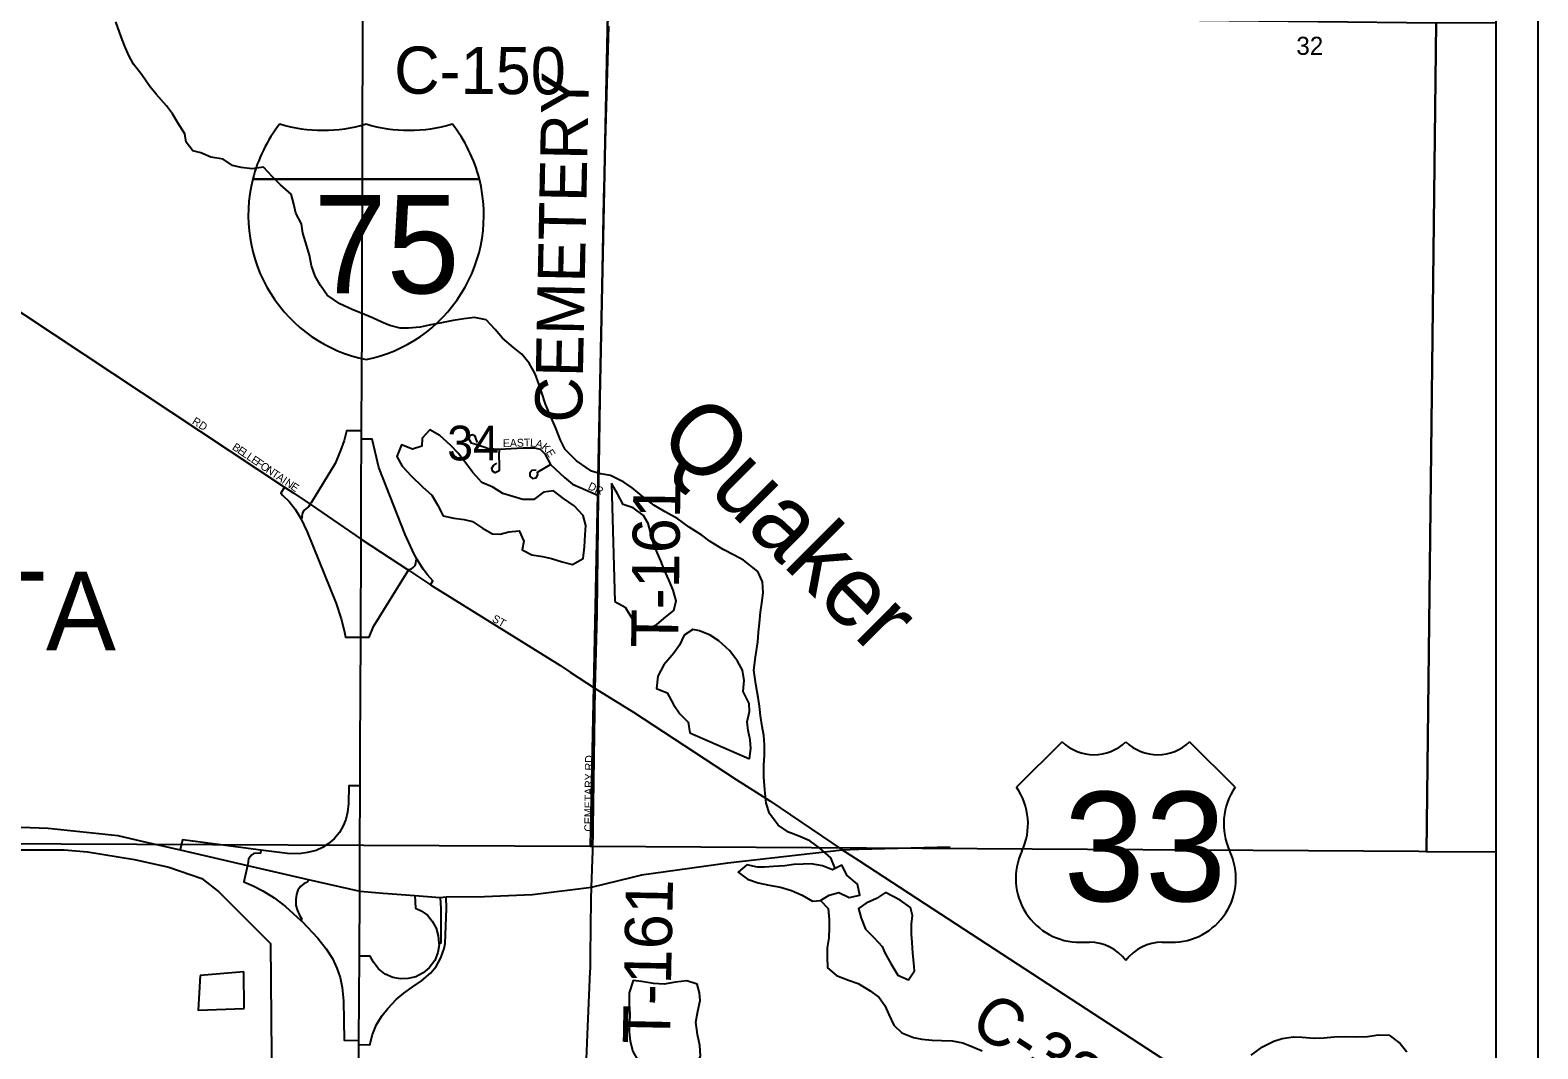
# Model space of a CAD drawing. Extents: x -784 to 1375, y -225 to 440.
# Drawn here: x 133.1 to 205.1, y 307.5 to 356.1 of the extents above; entities that cross this region are included whole.
import ezdxf

# ---------------------------------------------------------------- set-up
doc = ezdxf.new("R2010")
doc.units = 0
for name, color, linetype in [('GM_X_City_Street', 7, 'Continuous'), ('GM_X_City_Street_Text', 7, 'Continuous'), ('GM_X_Corporation_Text', 7, 'Continuous'), ('GM_X_County_Road', 7, 'Continuous'), ('GM_X_County_Road_Text', 7, 'Continuous'), ('GM_X_Interchange_Ramps', 7, 'Continuous'), ('GM_X_Interstate_Route', 7, 'Continuous'), ('GM_X_Interstate_Shield', 7, 'Continuous'), ('GM_X_Minor_Lake', 7, 'Continuous'), ('GM_X_Minor_River', 7, 'Continuous'), ('GM_X_Minor_River_Text', 7, 'Continuous'), ('GM_X_Section', 7, 'Continuous'), ('GM_X_Section_Text', 7, 'Continuous'), ('GM_X_Township_Road', 7, 'Continuous'), ('GM_X_Township_Road_Text', 7, 'Continuous'), ('GM_X_Township_Subdivision', 7, 'Continuous'), ('GM_X_Township_Subdivision_Text', 7, 'Continuous'), ('GM_X_US_Location', 7, 'Continuous'), ('GM_X_US_Route', 7, 'Continuous'), ('GM_X_US_Shield', 7, 'Continuous'), ('SH_Data', 7, 'Continuous'), ('SH_Text', 7, 'Continuous')]:
    doc.layers.add(name, color=color, linetype=linetype)

msp = doc.modelspace()

# ---------------------------------------------------------------- linework, layer by layer
at = {"layer": 'GM_X_City_Street'}
for points in [[(126.452, 346.784), (128.669, 345.259), (142.616, 336.025)], [(142.616, 336.025), (145.259, 334.275), (145.695, 333.991), (146.472, 333.461), (148.912, 331.797), (151.169, 330.314), (152.221, 329.626), (158.401, 325.779), (158.893, 325.455)], [(158.893, 325.455), (160.087, 324.667)], [(159.906, 315.192), (159.967, 316.92), (160.087, 324.667)], [(129.862, 302.524), (129.911, 316.968), (134.73, 316.967), (135.85, 316.872), (138.098, 316.511), (139.727, 316.14), (141.314, 315.604), (142.118, 314.974), (144.593, 312.499), (144.675, 301.856), (146.016, 301.248)]]:
    msp.add_lwpolyline(points, dxfattribs=at)
at = {"layer": 'GM_X_County_Road'}
for points in [[(160.087, 324.667), (161.91, 323.537), (164.313, 321.971), (166.824, 320.321), (168.42, 319.311), (171.871, 316.977)], [(171.871, 316.977), (172.668, 316.458), (175.843, 314.388)], [(175.843, 314.388), (191.895, 303.924), (193.049, 303.183), (193.82, 302.693), (195.033, 301.892), (196.331, 301.073), (199.02, 299.303)]]:
    msp.add_lwpolyline(points, dxfattribs=at)
at = {"layer": 'GM_X_Interchange_Ramps'}
for points in [[(148.933, 336.967), (148.218, 336.97), (148.215, 336.954), (148.106, 336.508), (147.932, 336.024), (147.667, 335.414), (146.525, 333.538), (146.472, 333.461)], [(152.221, 329.626), (152.34, 329.807), (152.078, 330.094), (151.879, 330.367), (151.595, 330.834), (151.446, 331.08), (151.017, 332.023), (149.765, 335.222), (149.576, 335.968), (149.443, 336.563), (148.931, 336.566)], [(145.259, 334.275), (145.076, 333.992), (145.182, 333.888), (145.484, 333.589), (145.761, 333.222), (146.029, 332.782), (146.341, 332.151), (147.728, 328.721), (147.967, 328.001), (148.104, 327.446), (148.16, 327.127), (148.893, 327.124)], [(146.472, 333.461), (146.393, 333.346), (146.266, 333.253), (146.185, 333.168), (146.111, 333.05), (146.092, 332.975), (146.087, 332.881), (146.099, 332.824), (146.029, 332.782)], [(151.169, 330.314), (151.194, 330.353), (151.322, 330.384), (151.404, 330.442), (151.487, 330.541), (151.529, 330.641), (151.533, 330.796), (151.595, 330.834)], [(148.893, 327.124), (149.298, 327.121), (149.511, 327.624), (151.057, 330.143), (151.169, 330.314)], [(148.865, 320.03), (148.331, 320.033), (148.302, 319.18), (148.258, 318.761), (148.181, 318.42), (148.06, 318.11), (147.876, 317.794), (147.626, 317.503), (147.346, 317.259), (147.07, 317.076), (146.771, 316.945), (146.352, 316.84), (145.961, 316.785), (145.39, 316.791), (144.126, 316.957), (140.882, 317.381), (140.383, 317.449), (140.273, 316.969)], [(144.126, 316.957), (144.105, 316.805), (143.795, 316.802), (143.697, 316.727), (143.593, 316.62), (143.531, 316.519), (143.515, 316.431), (143.521, 316.344), (143.494, 316.228)], [(143.494, 316.228), (143.313, 315.443), (143.752, 315.256), (144.218, 315.016), (144.756, 314.676), (145.306, 314.262), (146.038, 313.604), (146.099, 313.549), (146.853, 312.751), (147.242, 312.24), (147.544, 311.78), (147.76, 311.321), (147.915, 310.875), (148.008, 310.405), (148.074, 309.763), (148.11, 307.882), (148.807, 307.878)], [(146.387, 315.562), (146.357, 315.433), (146.187, 315.358), (146.023, 315.226), (145.887, 315.045), (145.821, 314.841), (145.796, 314.609), (145.8, 314.333), (145.853, 314.1), (145.963, 313.845), (146.088, 313.66), (146.038, 313.604)], [(148.806, 307.674), (149.324, 307.671), (149.454, 308.158), (149.652, 308.635), (149.919, 309.067), (150.185, 309.404), (150.583, 309.835), (150.945, 310.127), (151.35, 310.409), (151.798, 310.718), (152.222, 311.079), (152.488, 311.398), (152.72, 311.822), (152.874, 312.265), (152.92, 312.5), (152.994, 314.174), (152.971, 314.723)], [(151.472, 314.785), (151.511, 314.184), (151.771, 314.067), (152.083, 313.845), (152.297, 313.564), (152.493, 313.23), (152.585, 312.871), (152.624, 312.51), (152.632, 312.443), (152.575, 312.068), (152.43, 311.695), (152.155, 311.332), (151.873, 311.101), (151.531, 310.913), (151.163, 310.831), (150.796, 310.818), (150.431, 310.883), (150.058, 311.045), (149.747, 311.293), (149.498, 311.602), (149.348, 311.892), (148.828, 311.894)], [(152.685, 314.703), (152.715, 314.169), (152.72, 312.52), (152.624, 312.51)]]:
    msp.add_lwpolyline(points, dxfattribs=at)
at = {"layer": 'GM_X_Interstate_Route'}
for points in [[(148.956, 342.85), (148.994, 356.971), (149.127, 363.092), (149.481, 366.399), (149.866, 368.87), (150.415, 371.5), (150.759, 372.833), (151.182, 374.134), (153.143, 379.365), (157.84, 391.358), (159.301, 395.248), (160.005, 397.139)], [(148.937, 338.143), (148.939, 338.63), (148.956, 342.806), (148.956, 342.85), (148.956, 342.85)], [(148.931, 336.566), (148.931, 336.566), (148.933, 336.967), (148.937, 338.143)], [(148.922, 334.182), (148.931, 336.566)], [(148.918, 333.387), (148.92, 333.903), (148.922, 334.182)], [(148.912, 331.797), (148.914, 332.327), (148.918, 333.387)], [(148.872, 321.803), (148.893, 327.124), (148.912, 331.797)], [(148.868, 320.739), (148.872, 321.803)], [(148.845, 314.996), (148.853, 316.941), (148.865, 320.03), (148.868, 320.739)], [(148.756, 298.078), (148.806, 307.674), (148.807, 307.878), (148.828, 311.894), (148.845, 314.996)]]:
    msp.add_lwpolyline(points, dxfattribs=at)
at = {"layer": 'GM_X_Interstate_Shield'}
for p, q in [((143.736, 348.98), (154.557, 348.98)), ((154.557, 348.98), (143.736, 348.98)), ((154.557, 348.98), (143.736, 348.98))]:
    msp.add_line(p, q, dxfattribs=at)
for centre, start, end in [((150.553, 347.256), 141.66896, 165.80665), ((147.092, 358.341), 253.00908, 286.99093), ((151.201, 358.341), 253.00908, 286.99093), ((147.74, 347.256), 14.19335, 38.33104), ((150.553, 347.256), 165.80665, 258.46304), ((147.74, 347.256), 281.53696, 14.19335)]:
    msp.add_arc(centre, 7.031, start, end, dxfattribs=at)
at = {"layer": 'GM_X_Minor_Lake'}
for points in [[(152.67, 336.751), (152.192, 337.013), (151.827, 336.612), (151.807, 336.237), (151.369, 336.093), (150.846, 336.295), (150.613, 335.742), (150.878, 335.288), (151.307, 334.816), (151.841, 334.298), (152.287, 333.901), (152.551, 333.432), (152.829, 332.917), (153.339, 332.805), (153.833, 332.738), (154.223, 332.643), (154.714, 332.32), (155.191, 332.058), (155.552, 332.039)], [(155.552, 332.039), (155.959, 332.153), (156.455, 332.191), (156.674, 331.708), (156.593, 331.288), (157.056, 331.056), (157.565, 330.974), (158, 330.878), (158.508, 330.721), (159.003, 330.594), (159.517, 330.872), (159.584, 331.427), (159.607, 331.998), (159.643, 332.448), (159.514, 332.931), (159.084, 333.387), (158.578, 333.74), (158.102, 334.107), (157.621, 334.039), (157.151, 333.684), (156.625, 333.692), (155.682, 333.975), (155.206, 334.282), (154.668, 334.5), (154.239, 334.987), (153.87, 335.488), (153.545, 335.898), (153.174, 336.278), (152.67, 336.751)], [(160.871, 334.46), (161.022, 328.823)], [(163.035, 327.728), (163.461, 328.098), (163.84, 328.393), (163.952, 328.858), (163.808, 329.371), (163.604, 329.854), (163.386, 330.353), (163.226, 330.761), (163.051, 331.154), (162.891, 331.547), (162.733, 332.135), (162.618, 332.542), (162.398, 332.921), (161.907, 333.289), (161.429, 333.445), (161.15, 333.96), (160.871, 334.46)], [(161.022, 328.823), (161.514, 328.546), (161.838, 328.03), (162.043, 327.652), (162.582, 327.509), (163.035, 327.728)], [(165.074, 327.43), (164.745, 327.494), (164.336, 327.215), (164.104, 326.737), (163.844, 326.35), (163.356, 325.801), (163.078, 325.263), (163.01, 324.678), (163.518, 324.461), (163.826, 323.901), (164.121, 323.461), (164.521, 323.065), (164.605, 322.553)], [(167.457, 321.312), (167.524, 321.806), (167.484, 322.228), (167.385, 322.665), (167.345, 323.086), (167.457, 323.58), (167.432, 323.956), (167.154, 324.531), (167.206, 325.056), (167.123, 325.553), (166.873, 325.977), (166.519, 326.463), (165.984, 326.951), (165.582, 327.212), (165.074, 327.43)], [(164.605, 322.553), (167.457, 321.312)], [(167.839, 316.138), (167.33, 316.25), (166.905, 315.91), (167.351, 315.574), (167.86, 315.401), (168.399, 315.289), (168.938, 315.191), (169.462, 315.034), (169.97, 314.801), (170.462, 314.524), (170.838, 314.549)], [(170.838, 314.549), (171.262, 314.813), (171.714, 314.927), (172.207, 314.695), (172.719, 314.808), (172.606, 315.336), (172.115, 315.748), (171.867, 316.247), (171.413, 316.013), (170.935, 316.2), (170.395, 316.298), (170.02, 316.288), (169.569, 316.264), (169.132, 316.21), (168.606, 316.172), (168.17, 316.148), (167.839, 316.138)], [(173.953, 314.941), (173.513, 314.647), (173.029, 314.428), (172.651, 314.178), (172.78, 313.711), (172.983, 313.182), (173.383, 312.786), (173.783, 312.36), (173.914, 312.057)], [(173.914, 312.057), (174.193, 311.543), (174.531, 310.997), (175.039, 310.765), (175.33, 311.196), (175.305, 311.572), (175.251, 312.039), (175.213, 312.55), (175.188, 312.941), (175.194, 313.422), (175.23, 313.842), (175.145, 314.219), (174.639, 314.571), (173.953, 314.941)], [(141.227, 310.976), (141.13, 309.325), (143.324, 309.4)], [(143.318, 311.143), (141.227, 310.976)], [(143.324, 309.4), (143.318, 311.143)], [(164.469, 310.714), (163.921, 310.648), (163.379, 310.566), (162.869, 310.588), (162.299, 310.686), (161.894, 310.737), (161.706, 310.153), (161.714, 309.612), (161.738, 309.131), (161.717, 308.711), (161.711, 308.276), (161.751, 307.839), (161.879, 307.342), (162.129, 306.933), (162.637, 306.686)], [(162.637, 306.686), (162.981, 306.576), (163.46, 306.509), (163.985, 306.441), (164.466, 306.45), (164.919, 306.609), (165.121, 307.147), (165.083, 307.628), (164.969, 308.155), (164.887, 308.742), (164.984, 309.267), (165.096, 309.776), (165.071, 310.152), (164.956, 310.559), (164.469, 310.714)]]:
    msp.add_lwpolyline(points, dxfattribs=at)
at = {"layer": 'GM_X_Minor_River'}
for points in [[(139.126, 353.028), (138.83, 353.408), (138.447, 353.954), (138.048, 354.47), (137.828, 354.879), (137.61, 355.362), (137.45, 355.77), (137.204, 356.495)], [(171.549, 316.083), (171.33, 316.585), (170.811, 317.043), (170.335, 317.395), (169.782, 317.643), (169.319, 317.815), (168.828, 318.152), (168.414, 318.699), (168.256, 319.197), (168.189, 319.829), (168.137, 320.461), (168.144, 321.017), (168.166, 321.482), (168.172, 321.978), (168.133, 322.429), (168.063, 322.851), (167.98, 323.363), (167.926, 323.829), (167.871, 324.236), (167.76, 324.883), (167.663, 325.546), (167.732, 326.161), (167.846, 326.896), (167.883, 327.361), (167.933, 327.796), (167.985, 328.321), (168.053, 328.861), (168.103, 329.251), (168.079, 329.763), (167.846, 330.247), (167.162, 330.797), (166.729, 331.028), (166.192, 331.306), (165.581, 331.69), (165.18, 331.981), (164.569, 332.365), (164.033, 332.763), (163.422, 333.102), (162.885, 333.425), (162.395, 333.808), (161.845, 334.251), (161.458, 334.512), (160.816, 334.836), (160.336, 334.918), (159.917, 335.044), (159.188, 335.535), (158.654, 336.083), (158.435, 336.522), (158.202, 337.096), (157.94, 337.716), (157.721, 338.245), (157.533, 338.788), (157.389, 339.211), (157.215, 339.694), (156.936, 340.194), (156.581, 340.634), (156.18, 340.94), (155.66, 341.383), (155.305, 341.809), (154.875, 342.266), (154.321, 342.378), (153.81, 342.31), (153.313, 342.227), (152.756, 342.129), (152.153, 342.017), (151.732, 341.918), (151.175, 341.865), (150.77, 341.871), (150.29, 341.998), (149.902, 342.153), (149.454, 342.355), (149.066, 342.525), (148.483, 342.759), (147.901, 343.022), (147.29, 343.436), (146.966, 343.906), (146.717, 344.346), (146.543, 344.844), (146.444, 345.356), (146.258, 345.99), (146.128, 346.397), (146.059, 346.849), (145.795, 347.348), (145.696, 347.785), (145.567, 348.268), (145.062, 348.71), (144.662, 349.106), (144.247, 349.548), (143.705, 349.465), (143.18, 349.532), (142.776, 349.628), (142.329, 349.935), (141.745, 350.033), (141.267, 350.235), (140.877, 350.33), (140.552, 350.74), (140.498, 351.147), (140.159, 351.662), (139.91, 352.101), (139.614, 352.481), (139.126, 353.028)], [(170.838, 314.549), (171.208, 314.168), (171.261, 313.642), (171.256, 313.266), (171.235, 312.771), (171.168, 312.291), (171.163, 311.87), (171.171, 311.344), (171.602, 310.978), (172.184, 310.744), (172.633, 310.588), (173.214, 310.249), (173.646, 309.928), (173.911, 309.549), (174.1, 309.11), (174.349, 308.611), (174.72, 308.231), (175.288, 308.012), (175.677, 307.932), (176.172, 307.895), (176.623, 307.874), (177.133, 307.852), (177.643, 307.754), (178.151, 307.552), (178.554, 307.381)], [(191.41, 307.173), (191.941, 307.571), (192.485, 307.834), (192.877, 307.963), (193.419, 308.046), (193.84, 308.025), (194.41, 307.987), (194.876, 307.996), (195.372, 308.049), (195.928, 308.056), (196.439, 308.049), (196.95, 308.057), (197.476, 308.14), (197.987, 308.118), (198.523, 307.735), (198.833, 307.325)]]:
    msp.add_lwpolyline(points, dxfattribs=at)
at = {"layer": 'GM_X_Section'}
for points in [[(120.755, 357.05), (160.697, 356.887), (159.863, 317.136), (120.146, 317.31)], [(160.697, 356.887), (200.23, 356.446), (199.773, 316.883), (199.413, 316.89), (159.863, 317.136)]]:
    msp.add_lwpolyline(points, close=True, dxfattribs=at)
msp.add_lwpolyline([(203.088, 316.862), (199.773, 316.883), (200.23, 356.446), (203.088, 356.455)], dxfattribs=at)
at = {"layer": 'GM_X_Township_Road'}
for points in [[(160.27, 335.289), (160.319, 338.516), (160.404, 342.989), (160.499, 348.034), (160.739, 356.287)], [(160.175, 328.208), (160.177, 328.29), (160.212, 331.058), (160.225, 332.414), (160.248, 333.885), (160.27, 335.289)], [(160.087, 324.667), (160.175, 328.208)], [(159.708, 307.774), (159.851, 311.165), (159.857, 311.312), (159.864, 311.926), (159.894, 314.593), (159.906, 315.192)], [(159.643, 306.213), (159.643, 306.215), (159.707, 307.738), (159.708, 307.774)]]:
    msp.add_lwpolyline(points, dxfattribs=at)
at = {"layer": 'GM_X_Township_Subdivision'}
for points in [[(154.462, 336.414), (154.411, 336.564), (154.36, 336.713), (154.235, 336.778), (154.079, 336.731), (154.049, 336.569), (154.169, 336.39), (154.505, 336.303), (154.988, 336.127), (155.496, 336.091), (156.644, 336.156), (157.182, 336.156), (157.463, 336.091), (157.684, 335.87), (157.947, 335.361), (158.616, 334.74), (158.999, 334.429), (160.248, 333.885)], [(155.496, 336.091), (155.485, 335.793), (155.496, 335.361), (155.496, 335.063), (155.305, 334.967), (155.191, 335.045), (155.155, 335.182), (155.227, 335.308), (155.394, 335.421)], [(157.271, 335.087), (157.068, 335.069), (156.973, 334.955), (156.973, 334.806), (157.086, 334.692), (157.265, 334.722), (157.343, 334.865), (157.325, 334.997), (157.947, 335.361)]]:
    msp.add_lwpolyline(points, dxfattribs=at)
at = {"layer": 'GM_X_US_Route'}
for points in [[(130.73, 318.111), (130.951, 318.111), (133.972, 318.009), (137.293, 317.66), (138.45, 317.389), (140.273, 316.969), (143.494, 316.228), (146.387, 315.562), (148.845, 314.996), (149.595, 314.936)], [(161.804, 315.654), (162.186, 315.747), (162.301, 315.785), (166.419, 316.356), (171.871, 316.977), (172.645, 316.997), (172.667, 316.997)], [(172.667, 316.997), (177.04, 317.109)], [(159.906, 315.192), (161.804, 315.654)], [(149.595, 314.936), (149.971, 314.906)], [(149.971, 314.906), (151.472, 314.785), (152.685, 314.703), (152.971, 314.723), (154.807, 314.744), (157.093, 314.846), (159.906, 315.192)]]:
    msp.add_lwpolyline(points, dxfattribs=at)
at = {"layer": 'GM_X_US_Shield'}
for p, q in [((182.375, 322.132), (180.199, 319.957)), ((190.641, 319.957), (188.466, 322.132)), ((183.245, 312.561), (183.68, 312.561)), ((187.16, 312.561), (187.595, 312.561))]:
    msp.add_line(p, q, dxfattribs=at)
for centre, radius, start, end in [((183.897, 323.686), 2.175, 225.573, 314.427), ((186.943, 323.686), 2.175, 225.573, 314.427), ((177.705, 318.21), 3.045, 334.54712, 35.00093), ((193.135, 318.21), 3.045, 144.99907, 205.45288), ((183.211, 315.606), 3.045, 154.83192, 270.63826), ((187.629, 315.606), 3.045, 269.36174, 25.16808), ((183.68, 310.386), 2.175, 36.8699, 90), ((187.16, 310.386), 2.175, 90, 143.1301)]:
    msp.add_arc(centre, radius, start, end, dxfattribs=at)
at = {"layer": 'SH_Data'}
msp.add_line((205.088, 421.485), (205.088, 281.485), dxfattribs=at)
at = {"layer": 'SH_Text'}
msp.add_lwpolyline([(67.088, 419.485), (203.088, 419.485), (203.088, 283.485), (67.088, 283.485)], close=True, dxfattribs=at)

# ---------------------------------------------------------------- texts
at = {"layer": 'GM_X_City_Street_Text'}
for s, rotation, p in [('RD', 327.98725, (140.809, 337.331)), ('B', 325.77787, (142.725, 336.108)), ('E', 325.77343, (142.971, 335.941)), ('L', 325.77343, (143.189, 335.793)), ('L', 325.77343, (143.407, 335.644)), ('E', 325.76442, (143.625, 335.496)), ('F', 325.77343, (143.844, 335.347)), ('O', 325.76605, (144.062, 335.199)), ('N', 325.78159, (144.335, 335.013)), ('T', 325.76442, (144.608, 334.828)), ('A', 325.78159, (144.826, 334.679)), ('I', 325.78864, (145.099, 334.494)), ('N', 325.77635, (145.235, 334.401)), ('E', 326.66275, (145.514, 334.212)), ('ST', 330.24504, (155.128, 327.894)), ('CEMETARY RD', 89.42158, (159.94, 317.835))]:
    msp.add_text(s, height=0.375, rotation=rotation, dxfattribs=at).set_placement(p)
at = {"layer": 'GM_X_Corporation_Text'}
msp.add_text('WAPAKONETA', height=3.75, rotation=0.00001, dxfattribs=at).set_placement((101.822, 326.489))
at = {"layer": 'GM_X_County_Road_Text'}
for s, rotation, p in [('C-150', 359.72445, (150.483, 353.063)), ('C-33A', 326.87036, (177.872, 308.422))]:
    msp.add_text(s, height=2.25, rotation=rotation, dxfattribs=at).set_placement(p)
at = {"layer": 'GM_X_Interstate_Shield'}
msp.add_text('75', height=4.6875, dxfattribs=at).set_placement((146.641, 343.531))
at = {"layer": 'GM_X_Minor_River_Text'}
msp.add_text('Quaker', height=3.375, rotation=315.02199, dxfattribs=at).set_placement((162.962, 336.572))
at = {"layer": 'GM_X_Section_Text'}
for s, height, p in [('32', 0.8633, (193.56, 354.912)), ('34', 1.6575, (153.023, 335.557))]:
    msp.add_text(s, height=height, rotation=0.00001, dxfattribs=at).set_placement(p)
at = {"layer": 'GM_X_Township_Road_Text'}
for s, rotation, p in [('CEMETERY', 88.85191, (159.455, 337.342)), ('T-161', 89.16938, (164.047, 326.599)), ('T-161', 88.87659, (163.65, 307.697))]:
    msp.add_text(s, height=2.25, rotation=rotation, dxfattribs=at).set_placement(p)
at = {"layer": 'GM_X_Township_Subdivision_Text'}
for s, rotation, p in [('EAST', 1.68149, (155.684, 336.187)), ('L', 356.50036, (156.968, 336.22)), ('A', 344.60109, (157.211, 336.207)), ('K', 318.74213, (157.49, 336.141)), ('E', 301.54485, (157.719, 335.946)), ('DR', 334.80321, (159.71, 334.2))]:
    msp.add_text(s, height=0.375, rotation=rotation, dxfattribs=at).set_placement(p)
at = {"layer": 'GM_X_US_Location'}
for s in ['/', '0']:
    msp.add_text(s, height=0.0075, dxfattribs=at).set_placement((185.418, 317.088))
msp.add_text('33', height=0.0075, rotation=0.00001, dxfattribs=at).set_placement((183.869, 315.535))
at = {"layer": 'GM_X_US_Shield'}
msp.add_text('33', height=5.2207, dxfattribs=at).set_placement((182.448, 314.519))

doc.saveas('drawing.dxf')
